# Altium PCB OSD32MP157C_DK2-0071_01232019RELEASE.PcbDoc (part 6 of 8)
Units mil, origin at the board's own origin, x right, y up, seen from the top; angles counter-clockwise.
Board outline 3976.38 x 2795.28 mil, 6 copper layers (Top Layer, Signal Layer 1, Signal Layer 2, Signal Layer 3, Signal Layer 4, Bottom Layer), stack 61.268 mil thick; 404 components, 418 nets, 1720 pads, 1233 vias.
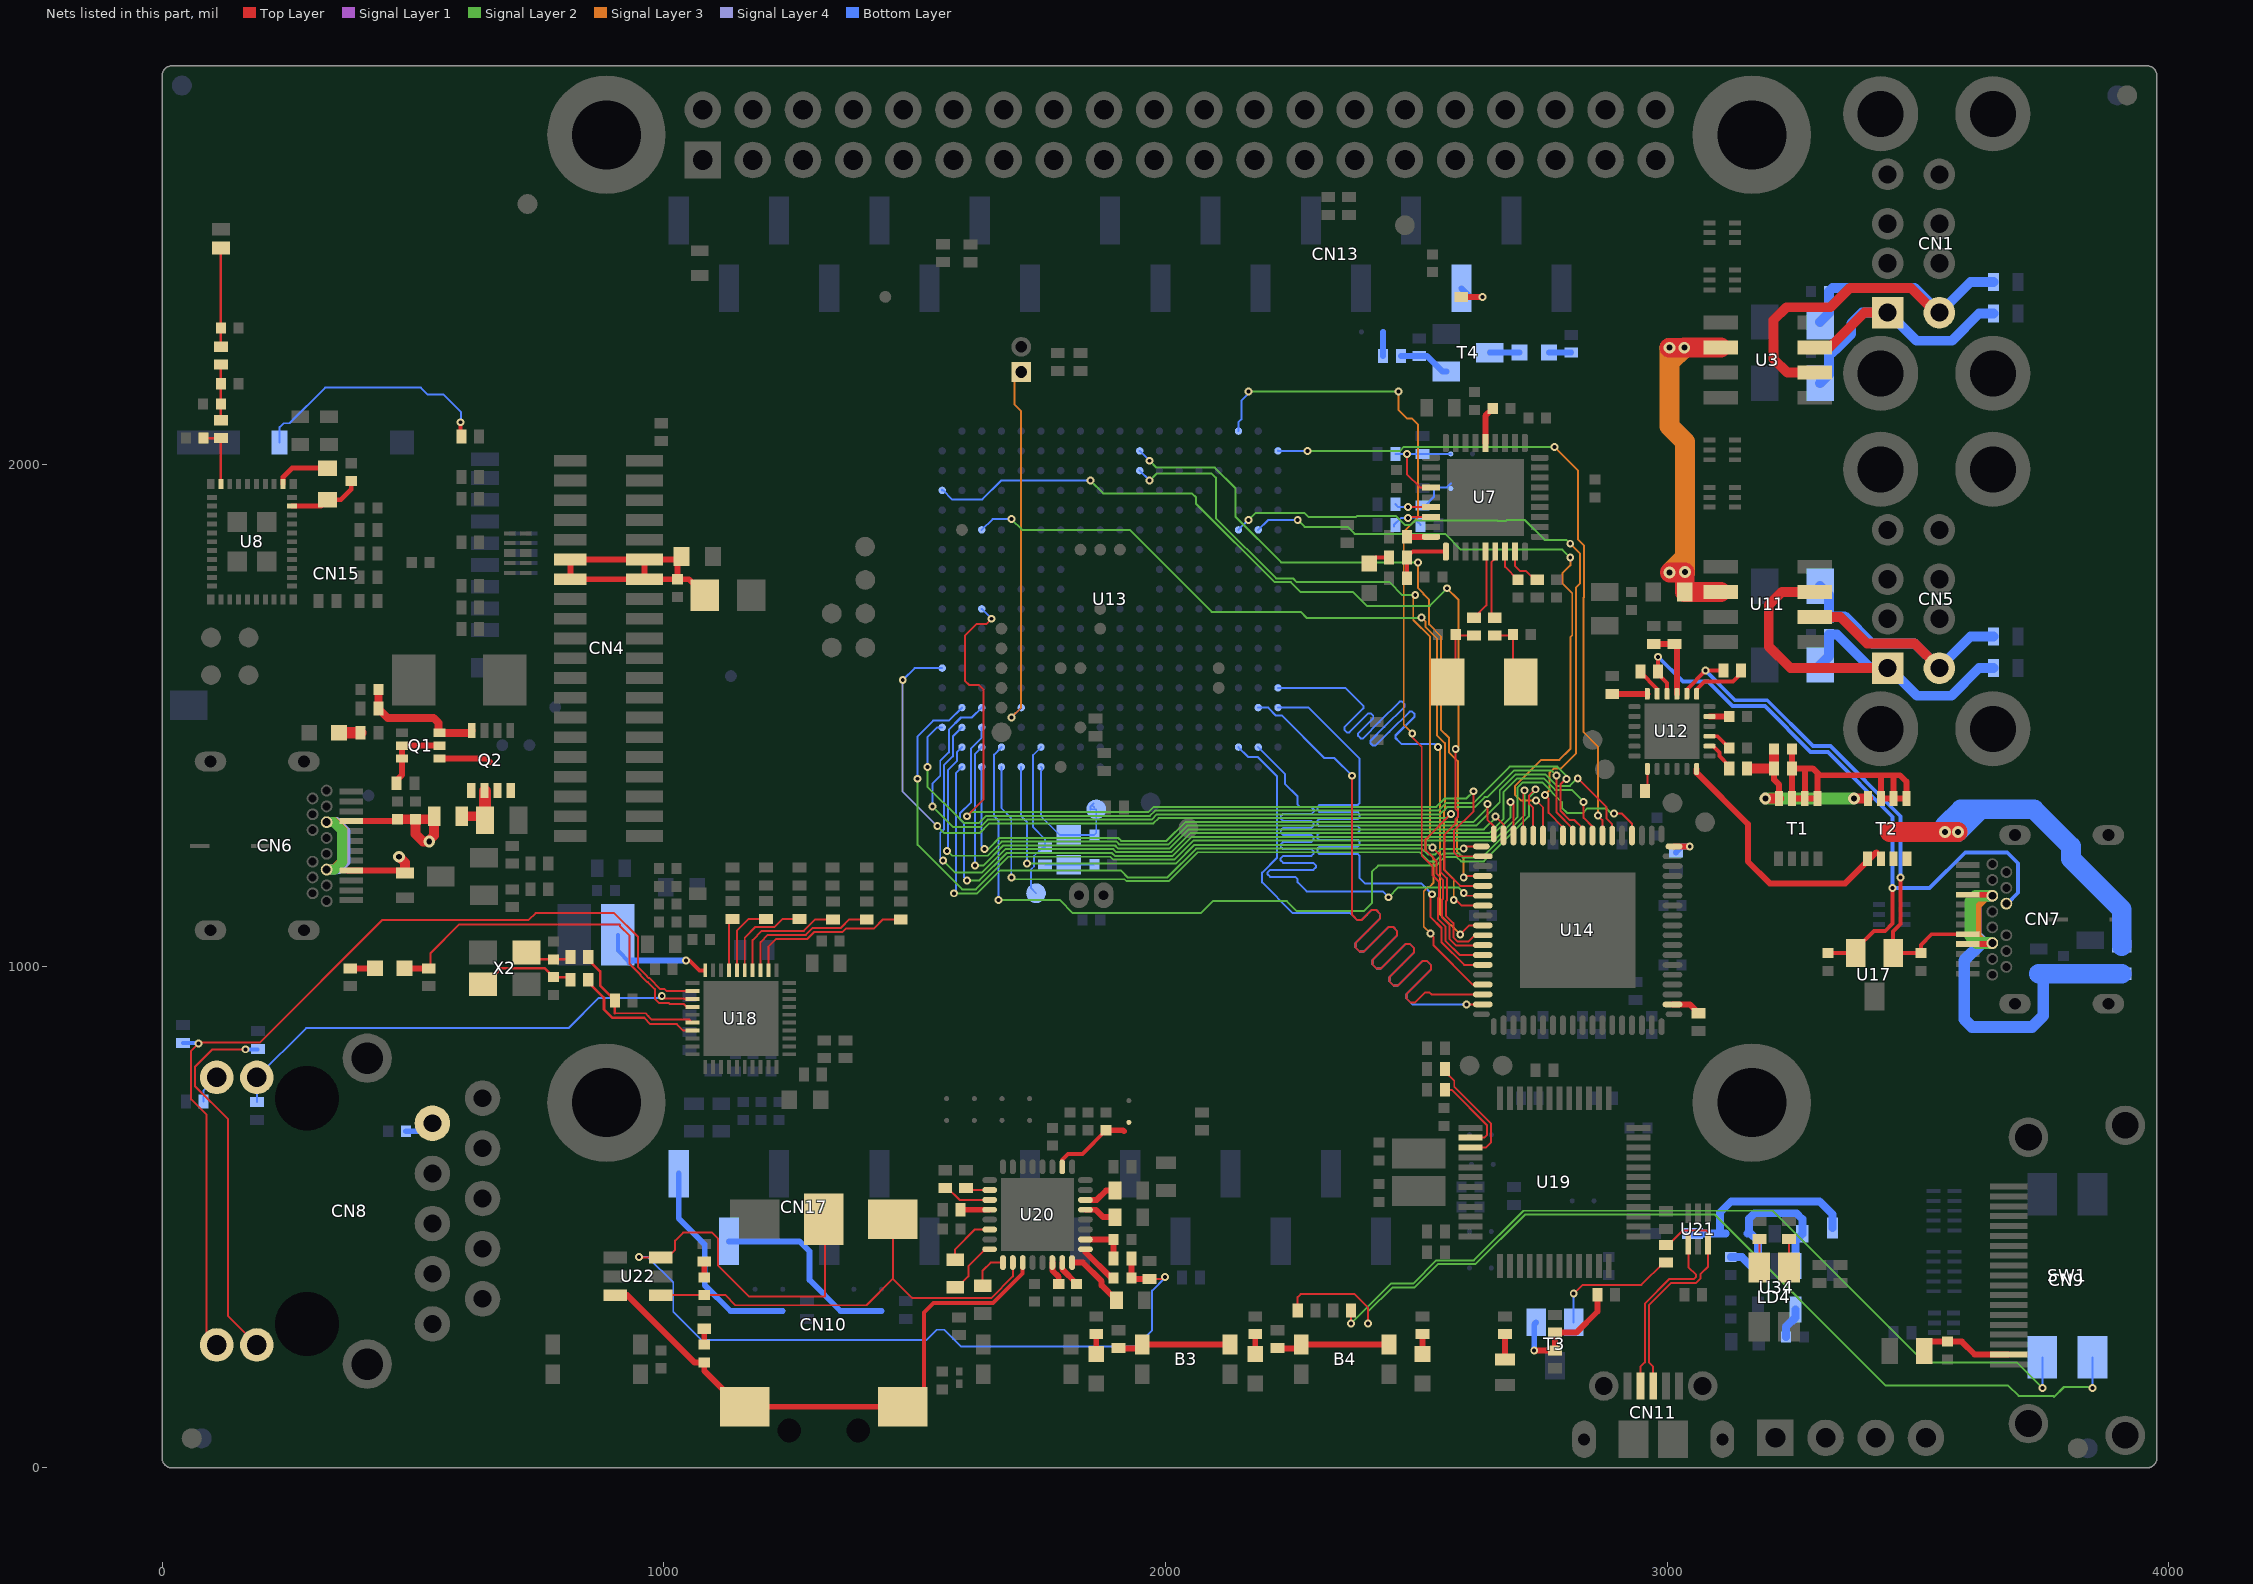
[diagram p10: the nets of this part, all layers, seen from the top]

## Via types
v1: diameter 15.75, hole 7.87, Top Layer to Bottom Layer, tented both sides, 803 vias
v2: diameter 23.62, hole 11.81, Top Layer to Bottom Layer, tented both sides, 417 vias
v3: diameter 15.75, hole 7.87, Top Layer to Bottom Layer, 13 vias

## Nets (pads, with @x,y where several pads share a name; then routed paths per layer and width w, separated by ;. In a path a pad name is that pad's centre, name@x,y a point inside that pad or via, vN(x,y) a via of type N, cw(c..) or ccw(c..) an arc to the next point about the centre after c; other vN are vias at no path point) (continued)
LTDC_B1: U13.A4 U14.31 | length 1444.4
  Top Layer w3.94: v1(2531.49,1143.7) 2531.01,1144.18 2528.62,1144.18 2528.62,1098.2 2550.39,1076.44 2550.39,1048.09 2595.53,1002.95 U14.31@2632.87,1002.95
  Bottom Layer w3.94: U13.A4@2224.41,1515.75 2285.43,1515.75 2386.56,1414.62 2386.56,1342.52 2386.56,1335.55 2386.56,1325.1 2383.07,1321.61 2306.78,1321.61 2303.29,1318.13 2303.29,1311.16 2306.78,1307.68 2383.07,1307.68 2386.56,1304.19 2386.56,1297.22 2383.07,1293.74 2306.63,1293.74 2303.15,1290.26 2303.15,1283.29 2306.63,1279.8 2383.07,1279.8 2386.56,1276.32 2386.56,1269.35 2383.07,1265.87 2306.63,1265.87 2303.15,1262.38 2303.15,1255.41 2306.63,1251.93 2383.07,1251.93 2386.56,1248.44 2386.56,1241.48 2383.07,1237.99 2306.63,1237.99 2303.15,1234.51 2303.15,1227.54 2306.63,1224.06 2383.07,1224.06 2386.56,1220.57 2386.56,1210.63 2386.56,1176.43 2397.64,1165.35 2509.84,1165.35 v1(2531.49,1143.7)
LTDC_B2: U13.C18 U14.30 | length 1636.8
  Top Layer w3.94: v1(2492.13,1464.57) 2492.13,1456.69 2511.02,1437.8 2511.02,1220.87 2532.48,1199.41 2532.48,1181.95 2545.27,1169.16 2545.27,1137.99 2543.26,1135.98 2543.26,1094.7 2558.27,1079.7 2558.27,1051.35 2586.98,1022.64 U14.30@2632.87,1022.64
  Signal Layer 2 w3.94: v1(2165.35,2145.66) v1(2464.56,2145.66)
  Signal Layer 3 w3.94: v1(2464.56,2145.66) 2464.56,2109.37 2481.41,2092.52 2490.91,2092.52 2503.94,2079.49 2503.94,1894.88 2475.14,1866.09 2475.14,1481.55 v1(2492.13,1464.57)
  Bottom Layer w3.94: U13.C18@2145.67,2066.93 2145.67,2084.65 2151.57,2090.55 2151.57,2127.95 2165.35,2141.73 v1(2165.35,2145.66)
LTDC_B3: U13.V6 U14.29 | length 1817.3
  Top Layer w3.94: v1(2569.09,1303.74) 2518.9,1253.54 2518.9,1231.1 2526.97,1223.03 2527.56,1223.03 2540.35,1210.24 2540.35,1185.21 2553.14,1172.42 2553.14,1134.73 2551.14,1132.72 2551.14,1097.97 2566.14,1082.96 2566.14,1054.61 2578.83,1041.93 2632.48,1041.93 U14.29@2632.87,1042.32
  Signal Layer 2 w3.94: v1(1545.28,1279.53) 1559.06,1265.75 1629.38,1265.75 1648.67,1285.04 1975.98,1285.04 1986.42,1295.47 2560.83,1295.47 v1(2569.09,1303.74)
  Signal Layer 4 w3.94: v1(1476.38,1570.87) 1476.38,1348.43 v1(1545.28,1279.53)
  Bottom Layer w3.94: v1(1476.38,1570.87) 1500,1594.49 U13.V6@1555.12,1594.49
LTDC_B4: U13.P1 U14.28 | length 1288.9
  Top Layer w3.94: v1(2532.68,1236.81) 2548.23,1221.26 2548.23,1188.47 2561.02,1175.68 2561.02,1131.47 2559.01,1129.46 2559.01,1101.23 2574.02,1086.22 2574.02,1057.88 2582.09,1049.8 2604.53,1049.8 2616.73,1062.01 U14.28@2632.87,1062.01
  Signal Layer 2 w3.94: v1(1724.41,1204.72) 2020.42,1204.72 2058.02,1242.32 2527.17,1242.32 v1(2532.68,1236.81)
  Bottom Layer w3.94: U13.P1@1712.6,1397.64 1712.6,1299.21 1724.41,1287.4 v1(1724.41,1204.72)
LTDC_B5: U13.A5 U14.27 | length 1331.9
  Top Layer w3.94: v1(2587.8,1063.58) 2605.91,1081.69 U14.27@2632.87,1081.69
  Signal Layer 3 w3.94: v1(2543.31,1437.01) 2547.24,1433.07 2547.24,1104.13 v1(2587.8,1063.58)
  Bottom Layer w3.94: U13.A5@2224.41,1555.12 2358.8,1555.12 2390.03,1523.89 2394.63,1519.29 2394.63,1514.36 2356.69,1476.42 2356.69,1471.49 2361.62,1466.56 2366.54,1466.56 2404.49,1504.51 2409.41,1504.51 2414.34,1499.58 2414.34,1494.65 2384.17,1464.48 2384.17,1459.55 2389.1,1454.62 2394.02,1454.62 2426.66,1487.26 2467.07,1527.67 2472,1527.67 2476.92,1522.74 2476.92,1517.81 2436.52,1477.41 2408.88,1449.77 2408.88,1444.85 2413.81,1439.92 2418.74,1439.92 2446.37,1467.55 2486.78,1507.96 2491.71,1507.96 2496.63,1503.03 2496.63,1498.1 2458.69,1460.16 2458.69,1455.23 2466.08,1447.84 2471.01,1442.91 2537.4,1442.91 v1(2543.31,1437.01)
LTDC_B6: U13.T13 U14.25 | length 1624.4
  Top Layer w3.94: v1(2574.8,1131.89) 2578.33,1131.89 2578.93,1132.49 2590.35,1121.06 U14.25@2632.87,1121.06
  Signal Layer 2 w3.94: v1(1692.91,1891.73) 1714.57,1870.08 1928.94,1870.08 2092.32,1706.69 2269.49,1706.69 2281.3,1694.88 2509.84,1694.88 v1(2510.29,1695.33)
  Signal Layer 3 w3.94: v1(2510.29,1695.33) 2518.11,1687.51 2518.11,1676.97 2541.34,1653.74 2541.34,1460.63 2557.09,1444.88 2557.09,1311.22 2555.31,1309.45 2555.31,1193.25 2574.8,1173.77 v1(2574.8,1131.89)
  Bottom Layer w3.94: U13.T13@1633.86,1870.08 1655.51,1891.73 v1(1692.91,1891.73) ; v1@2572.19,1131.89 v1(2574.8,1131.89)
LTDC_B7: U13.B2 U14.24 | length 1355
  Top Layer w3.94: v1@2594.68,1146.26 2600.2,1140.75 U14.24@2632.87,1140.75
  Signal Layer 2 w3.94: v1(2444.88,1137.8) 2464.56,1157.48 2583.52,1157.48 v1(2594.73,1146.27)
  Bottom Layer w3.94: U13.B2@2185.04,1437.01 2238.18,1383.86 2238.18,1364.18 2263.78,1338.58 2263.78,1327.36 2263.78,1322.48 2268.66,1317.6 2290.94,1317.6 2295.81,1312.72 2295.81,1308.54 2290.94,1303.66 2263.78,1303.66 2234.8,1303.66 2229.92,1298.78 2229.92,1294.6 2234.8,1289.72 2263.78,1289.72 2290.79,1289.72 2295.67,1284.85 2295.67,1280.67 2290.79,1275.79 2263.78,1275.79 2234.8,1275.79 2229.92,1270.91 2229.92,1266.73 2234.8,1261.85 2263.78,1261.85 2290.79,1261.85 2295.67,1256.97 2295.67,1252.79 2290.79,1247.91 2263.78,1247.91 2234.8,1247.91 2229.92,1243.04 2229.92,1238.85 2234.8,1233.98 2263.78,1233.98 2290.79,1233.98 2295.67,1229.1 2295.67,1224.92 2290.79,1220.04 2263.78,1220.04 2234.67,1220.04 2229.79,1215.16 2229.79,1210.98 2234.67,1206.1 2263.78,1206.1 2295.13,1206.1 2300.01,1201.22 2300.01,1197.04 2295.13,1192.17 2263.78,1192.17 2208.65,1192.17 2203.77,1187.29 2203.77,1183.11 2208.65,1178.23 2258.9,1178.23 2263.78,1173.35 2263.78,1171.26 2263.78,1167.32 2281.5,1149.61 2433.07,1149.61 v1(2444.88,1137.8)
LTDC_CLK: U13.H17 U14.22 | length 1387.7
  Top Layer w3.94: v1(2594.68,1176.77) 2598.03,1180.12 U14.22@2632.87,1180.12
  Signal Layer 2 w3.94: v1(1968.5,2007.87) 1982.28,1994.09 2098.43,1994.09 2139.76,1952.76 2139.76,1895.87 2230.51,1805.12 v1(2503.94,1805.12)
  Signal Layer 3 w3.94: v1(2503.94,1805.12) 2503.94,1753.74 2514.76,1742.91 2514.76,1741.68 2525.59,1730.85 2525.59,1681.64 2549.21,1658.02 2549.21,1471.99 2564.96,1456.24 2564.96,1427.17 2582.87,1409.25 2582.87,1298.03 2580.91,1296.06 2580.91,1229.13 2594.68,1215.36 v1(2594.68,1176.77)
  Bottom Layer w3.94: U13.H17@1948.82,2027.56 v1(1968.5,2007.87)
LTDC_DE: U13.H16 U14.33 | length 1583.9
  Top Layer w3.94: v1(2528.74,1065.55) 2527.76,1064.57 2534.65,1057.68 2534.65,1041.57 2612.63,963.58 U14.33@2632.87,963.58
  Signal Layer 2 w3.94: v1(1968.5,1968.5) 1982.28,1982.28 2092.32,1982.28 2100.39,1974.21 2100.39,1893.7 2220.87,1773.23 2254.33,1773.23 2261.81,1765.75 2446.85,1765.75 2472.44,1740.16 v1(2498.03,1740.16)
  Signal Layer 3 w3.94: v1(2498.03,1740.16) 2494.09,1736.22 2494.09,1690.41 2527.56,1656.95 2527.56,1259.25 2518.9,1250.59 2518.9,1231.1 2534.68,1215.32 2534.68,1167.14 2525.63,1158.08 2523.07,1158.08 2515,1150.01 2515,1079.29 v1(2528.74,1065.55)
  Bottom Layer w3.94: U13.H16@1948.82,1988.19 v1(1968.5,1968.5)
LTDC_G0: U13.V15 U14.23 | length 1833.5
  Top Layer w3.94: v1(2578.74,1433.07) 2578.74,1313.58 2582.87,1309.45 2582.87,1298.03 2578.74,1293.9 2578.74,1285.15 2556.1,1262.51 2556.1,1191.73 2587.4,1160.43 U14.23@2632.87,1160.43
  Signal Layer 2 w3.94: v1(1850.39,1968.5) 1875.98,1942.91 2052.95,1942.91 2061.02,1934.84 2061.02,1922.49 2217.77,1765.75 2250,1765.75 2269.68,1746.06 2374.02,1746.06 2401.57,1718.5 2527.02,1718.5 2561.25,1752.73 v1(2561.25,1753.71)
  Signal Layer 3 w3.94: v1(2561.25,1753.71) 2584.65,1730.31 2584.65,1438.98 v1(2578.74,1433.07)
  Bottom Layer w3.94: U13.V15@1555.12,1950.79 U13.V15@1555.12,1948.82 1556.81,1948.82 1574.53,1931.1 1634.93,1931.1 1672.33,1968.5 v1(1850.39,1968.5)
LTDC_G1: U13.T9 U14.20 | length 1729.5
  Top Layer w3.94: v1(1604.33,1299.21) 1637.8,1332.68 1637.8,1551.18 1627.95,1561.02 1608.47,1561.02 1600.39,1569.1 1600.39,1659.34 1623.34,1682.28 1642.91,1682.28 v1(1653.54,1692.91) ; v1(2614.37,1349.02) 2614.37,1309.65 2575.1,1270.37 2575.1,1227.07 2582.68,1219.49 U14.20@2632.87,1219.49
  Signal Layer 2 w3.94: v1(1604.33,1299.21) 1612.6,1307.48 1966.13,1307.48 1976.57,1317.91 2540.35,1317.91 2557.01,1334.57 2599.93,1334.57 v1(2614.37,1349.02)
  Bottom Layer w3.94: U13.T9@1633.86,1712.6 v1(1653.54,1692.91) v1@1653.54,1688.98
LTDC_G2: U13.U1 U14.19 | length 1369.6
  Top Layer w3.94: v1(2594.68,1234.84) 2599.02,1239.17 U14.19@2629.92,1239.17
  Signal Layer 2 w3.94: v1(1578.74,1145.67) 1624.68,1145.67 1669.95,1190.94 1911.61,1190.94 1925.39,1177.16 2003.44,1177.16 2061.12,1234.84 2511.22,1234.84 2523.03,1223.03 2538.38,1223.03 2549.21,1233.86 2593.7,1233.86 v1(2594.68,1234.84)
  Bottom Layer w3.94: v1(1578.74,1145.67) 1582.68,1149.61 1582.68,1385.83 U13.U1@1594.49,1397.64
LTDC_G3: U13.T1 U14.18 | length 1279.3
  Top Layer w3.94: v1(2641.93,1323.43) 2641.93,1292.4 2654.53,1279.8 U14.18@2654.53,1263.78
  Signal Layer 2 w3.94: v1(1639.76,1234.25) 1647.44,1234.25 1669.09,1255.91 1905.71,1255.91 1911.62,1250 2002.22,1250 2040.22,1287.99 2614.37,1287.99 2641.93,1315.55 v1(2641.93,1323.43)
  Bottom Layer w3.94: U13.T1@1633.86,1397.64 1633.86,1240.16 v1(1639.76,1234.25)
LTDC_G4: U13.T2 U14.17 | length 1372.1
  Top Layer w3.94: v1(2657.72,1298.83) 2657.72,1298.77 2674.21,1282.28 U14.17@2674.21,1260.83
  Signal Layer 2 w3.94: v1(1620.57,1200.79) 1636.92,1200.79 1677.08,1240.94 1899.51,1240.94 1905.42,1235.04 2008.42,1235.04 2046.41,1273.03 2634.84,1273.03 2659.18,1297.37 v1(2657.72,1298.83)
  Bottom Layer w3.94: v1(1620.57,1200.79) 1620.57,1423.72 U13.T2@1633.86,1437.01
LTDC_G5: U13.T3 U14.16 | length 1589.6
  Top Layer w3.94: U14.16@2693.9,1260.83 2693.9,1321.95 v1(2688.19,1327.66) ; v1(2688.19,1327.66) 2683.96,1331.89 2683.96,1323.43 v1(2688.19,1327.66)
  Signal Layer 2 w3.94: v1(1604.33,1171.26) 1629.11,1171.26 1683.83,1225.98 1893.32,1225.98 1899.22,1220.08 2014.62,1220.08 2052.61,1258.07 2648.85,1258.07 2688.19,1297.41 v1(2688.19,1327.66)
  Bottom Layer w3.94: v1(1604.33,1171.26) 1598.43,1177.17 1598.43,1285.63 1590.55,1293.51 1590.55,1304.92 1612.7,1327.07 1612.7,1434.64 1633.86,1455.8 U13.T3@1633.86,1476.38
LTDC_G6: U13.R1 U14.15 | length 1472.3
  Top Layer w3.54: U14.15@2713.58,1260.83 2713.58,1348.82 v1(2715.75,1350.98)
  Signal Layer 2 w3.54: v1(1692.91,1177.16) 1696.25,1173.82 1918.43,1173.82 1922.37,1169.88 2006.46,1169.88 2064.13,1227.56 2506.69,1227.56 2525.59,1208.66
  Signal Layer 2 w3.94: 2525.59,1208.66 2536.7,1208.66 2553.43,1225.39 2584.42,1225.39 2592.69,1217.13 2631.78,1217.13 2715.75,1301.1 v1(2715.75,1350.98)
  Bottom Layer w3.54: U13.R1@1673.23,1397.64 1673.23,1314.96 1692.91,1295.28 v1(1692.91,1177.16)
LTDC_G7: U13.R2 U14.14 | length 1684.3
  Top Layer w3.94: U14.14@2733.27,1260.83 2733.27,1315.95 2724.61,1324.61 2724.61,1340.16 v1(2737.42,1352.97)
  Signal Layer 2 w3.94: v1(1667.32,1131.89) 1789.93,1131.89 1815.53,1106.3 2070.87,1106.3 2094.49,1129.92 2242.32,1129.92 2262.01,1110.24 2395.67,1110.24 2411.42,1125.98 2411.42,1188.3 2423.9,1200.79 2539.4,1200.79 2556.14,1217.52 2581.16,1217.52 2589.42,1209.25 2635.04,1209.25 2724.61,1298.82 2724.61,1336.02 2739.42,1350.83 2737.42,1352.83 v1(2737.42,1352.97)
  Bottom Layer w3.94: v1(1667.32,1131.89) 1667.32,1289.96 1658.46,1298.82 1658.46,1422.24 U13.R2@1673.23,1437.01
LTDC_HSYNC: U13.B4 U14.34 | length 1439.9
  Top Layer w3.94: v1(2372.04,1379.92) 2372.04,1102.37 2374.02,1100.39 2382.41,1092 2390.87,1092 2411.36,1112.49 2419.82,1112.49 2428.29,1104.03 2428.29,1095.56 2403.57,1070.84 2378.85,1046.12 2378.85,1037.66 2387.31,1029.2 2395.77,1029.2 2420.49,1053.92 2445.21,1078.64 2453.68,1078.64 2462.14,1070.17 2462.14,1061.71 2437.42,1036.99 2412.7,1012.27 2412.7,1003.81 2421.16,995.34 2429.62,995.34 2454.34,1020.06 2479.07,1044.79 2487.53,1044.79 2495.99,1036.32 2495.99,1027.86 2471.27,1003.14 2446.55,978.42 2446.55,969.95 2455.01,961.49 2463.48,961.49 2488.2,986.21 2512.92,1010.93 2521.38,1010.93 2529.84,1002.47 2529.84,994.01 2505.12,969.29 2480.4,944.57 2480.4,936.1 2488.86,927.64 2497.33,927.64 2517.82,948.13 2526.28,948.13 2530.51,943.9 U14.34@2632.87,943.9
  Bottom Layer w3.94: U13.B4@2185.04,1515.75 2205.62,1515.75 2205.62,1514.66 2220.47,1499.8 2232.48,1499.8 2316.93,1415.35 2326.77,1415.35 2336.61,1415.35 v1(2372.04,1379.92)
LTDC_R0: U13.B13 U14.13 | length 1340.7
  Top Layer w3.54: v1(2738.39,1330.31) 2738.39,1331.3 2752.95,1316.73 U14.13@2752.95,1260.83
  Signal Layer 2 w3.94: v1(2263.78,1889.76) 2277.56,1875.98 2363.5,1875.98 2377.28,1862.2 2557.62,1862.2 2589.12,1830.71 2791.34,1830.71 v1(2807.09,1814.96)
  Signal Layer 3 w3.94: v1(2738.39,1330.31) 2709.06,1330.31 2696.85,1342.52 2696.85,1358.88 2749.39,1411.42 2785.24,1411.42 2807.09,1433.27 2807.09,1655.71 2811.02,1659.65 2811.02,1743.65 2791.34,1763.33 2791.34,1783.46 2807.09,1799.21 v1(2807.09,1814.96)
  Bottom Layer w3.94: U13.B13@2185.04,1870.08 2204.72,1889.76 v1(2263.78,1889.76)
LTDC_R1: U13.C13 U14.11 | length 1355.3
  Top Layer w3.94: v1(2756.32,1341.91) 2763.78,1334.45 2763.78,1305.91 2792.32,1277.36 U14.11@2792.32,1260.83
  Signal Layer 2 w3.94: v1(2165.35,1889.76) 2179.13,1903.54 2277.76,1903.54 2285.63,1895.67 2379.47,1895.67 2381.44,1897.64 2459.84,1897.64 2477.56,1879.92 2488.98,1879.92 2497.83,1888.78 2661.95,1888.78 2662.94,1887.8 2678.6,1887.8 2680.57,1889.76 2716.54,1889.76 2755.91,1850.39 2799.21,1850.39 v1(2807.09,1842.52)
  Signal Layer 3 w3.94: v1(2756.32,1341.91) 2765.94,1351.53 2765.94,1386.22 2774.02,1394.29 2787.99,1394.29 2818.9,1425.2 2818.9,1755.46 2826.77,1763.33 2826.77,1822.83 v1(2807.09,1842.52)
  Bottom Layer w3.94: U13.C13@2145.67,1870.08 v1(2165.35,1889.76) ; v1@2754.92,1340.51 v1(2756.32,1341.91)
LTDC_R2: U13.T4 U14.10 | length 1695.6
  Top Layer w3.94: v1(2779.72,1380.51) 2779.72,1306.69 2812.01,1274.41 U14.10@2812.01,1260.83
  Signal Layer 2 w3.94: v1(1535.43,1318.9) 1576.77,1277.56 1630.62,1277.56 1645.57,1292.52 1972.33,1292.52 1982.76,1302.95 2547.05,1302.95 2561.61,1317.52 2616.54,1317.52 2636.22,1337.2 2641.71,1337.2 2694.87,1390.37 2769.86,1390.37 v1(2779.72,1380.51)
  Bottom Layer w3.94: v1(1535.43,1318.9) 1535.43,1364.17 1551.18,1379.92 1551.18,1409.45 1568.41,1426.67 1568.41,1471.95 1592.52,1496.06 1614.17,1496.06 U13.T4@1633.86,1515.75
LTDC_R3: U13.V3 U14.9 | length 1642.8
  Top Layer w3.94: v1(2799.41,1373.62) 2798.43,1373.62 2787.6,1362.8 2787.6,1309.95 2805.47,1292.08 2814.55,1292.08 2831.69,1274.95 U14.9@2831.69,1260.83
  Signal Layer 2 w3.94: v1(1525.59,1397.64) 1525.59,1358.27 1588.58,1295.28 1588.78,1295.28 1598.62,1285.43 1627.91,1285.43 1642.47,1300 1969.23,1300 1979.66,1310.43 2543.95,1310.43 2558.91,1325.39 2613.27,1325.39 2686.13,1398.25 2781.48,1398.25 2799.41,1380.31 v1(2799.41,1373.62)
  Bottom Layer w3.94: v1(1525.59,1397.64) 1525.59,1456.69 1545.28,1476.38 U13.V3@1555.12,1476.38
LTDC_R4: U13.U3 U14.8 | length 1799.3
  Top Layer w3.94: v1(2833.86,1327.36) 2833.86,1295.87 2851.38,1278.35 U14.8@2851.38,1260.83
  Signal Layer 2 w3.94: v1(1557.09,1210.63) 1580.71,1187.01 1634.28,1187.01 1680.73,1233.46 1896.41,1233.46 1902.32,1227.56 2011.52,1227.56 2049.51,1265.55 2645.75,1265.55 2674.41,1294.21 2674.41,1347.64 2701.4,1374.62 2754.23,1374.62 2776.88,1351.97 2810.24,1351.97 2834.84,1327.36 v1(2833.86,1327.36)
  Bottom Layer w3.94: v1(1557.09,1210.63) 1561.02,1210.63 1555.12,1204.73 1551.18,1208.67 1551.18,1265.95 1559.06,1273.82 1559.06,1401.57 1576.28,1418.8 1576.28,1458.17 U13.U3@1594.49,1476.38
LTDC_R5: U13.A17 U14.7 | length 1371
  Top Layer w3.94: v1(2862.3,1300.43) 2871.06,1291.67 U14.7@2871.06,1260.83
  Signal Layer 2 w3.94: v1(2283.46,2027.56) 2467.72,2027.56 2475.59,2035.43 v1(2775.59,2035.43)
  Signal Layer 3 w3.94: v1(2775.59,2035.43) 2822.83,1988.19 2822.83,1850.59 2834.65,1838.78 2834.65,1736.22 2833.07,1734.65 2833.07,1467.37 2862.2,1438.24 2862.2,1300.53 v1(2862.3,1300.43)
  Bottom Layer w3.94: U13.A17@2224.41,2027.56 2224.41,2028.35 2225.2,2027.56 v1(2283.46,2027.56)
LTDC_R6: U13.U2 U14.6 | length 1725
  Top Layer w3.94: v1(2822.05,1374.61) 2879.54,1317.11 2879.54,1294.28 2890.75,1283.07 U14.6@2890.75,1260.83
  Signal Layer 2 w3.94: v1(1564.96,1230.31) 1574.8,1220.47 1645.47,1220.47 1673.42,1248.43 1902.61,1248.43 1908.52,1242.52 2005.32,1242.52 2043.32,1280.51 2619.69,1280.51 2666.54,1327.36 2666.54,1350.9 2698.13,1382.5 2757.49,1382.5 2780.14,1359.84 2806.3,1359.84 2822.05,1375.59 v1(2822.05,1374.61)
  Bottom Layer w3.94: v1(1564.96,1230.31) 1566.93,1232.28 1566.93,1391.73 1584.15,1408.96 1584.15,1426.67 U13.U2@1594.49,1437.01
LTDC_R7: U13.U4 U14.4 | length 1988.6
  Top Layer w3.94: v1(2893.95,1304.74) 2909.63,1304.74 2930.12,1284.25 U14.4@2930.12,1260.83
  Signal Layer 2 w3.94: v1(1505.91,1374.02) 1505.91,1242.32 1594.69,1153.54 1621.97,1153.54 1686.93,1218.5 1890.22,1218.5 1896.13,1212.6 2017.71,1212.6 2055.71,1250.59 2654.11,1250.59 2701.97,1298.45 2701.97,1356.69 2712.03,1366.75 2750.97,1366.75 2790.55,1327.16 2790.55,1316.09 2800.93,1305.71 2831.69,1305.71 2840.94,1314.96 2878.4,1314.96 2888.62,1304.74 v1(2893.95,1304.74)
  Bottom Layer w3.94: v1(1505.91,1374.02) 1505.91,1458.66 1536.91,1489.67 1568.41,1489.67 U13.U4@1594.49,1515.75
LTDC_VSYNC: U13.C2 U14.35 | length 1440.4
  Top Layer w3.94: v1(2600.39,924.21) U14.35@2632.87,924.21
  Bottom Layer w3.94: U13.C2@2145.67,1437.01 2165.35,1417.32 2184.15,1417.32 2222.44,1379.03 2222.44,1216.54 2192.91,1187.01 2192.91,1167.32 2253.94,1106.3 2368.11,1106.3 2382.41,1092 2390.87,1092 2411.36,1112.49 2419.82,1112.49 2428.29,1104.03 2428.29,1095.56 2378.85,1046.12 2378.85,1037.66 2387.31,1029.2 2395.77,1029.2 2445.21,1078.64 2453.68,1078.64 2462.14,1070.17 2462.14,1061.71 2412.7,1012.27 2412.7,1003.81 2421.16,995.34 2429.62,995.34 2479.07,1044.79 2487.53,1044.79 2495.99,1036.32 2495.99,1027.86 2446.55,978.42 2446.55,969.95 2455.01,961.49 2463.48,961.49 2512.92,1010.93 2521.38,1010.93 2529.84,1002.47 2529.84,994.01 2480.4,944.57 2480.4,936.1 2492.29,924.21 v1(2600.39,924.21)
NetB3_3: B3.3 B3.4 R110.1 | length 226.1
  Top Layer w11.81: R110.1@1906.5,239.17 1907.48,238.19 1945.87,238.19 B3.4@1953.74,246.06 B3.3@2128.94,246.06
NetB4_3: B4.3 B4.4 R111.1 | length 226.1
  Top Layer w11.81: R111.1@2223.43,239.17 2224.41,238.19 2262.8,238.19 B4.4@2270.67,246.06 B4.3@2445.87,246.06
NetC8_2: C8.2 L1.1 R8.1 | length 196.9
  Top Layer w5.12: R8.1@117.13,2235.24 C8.2@117.13,2272.64 L1.1@117.13,2432.09
NetC19_2: C19.2 C24.2 R8.2 R10.1 | length 111.2
  Top Layer w5.12: R10.1@117.13,2088.58 C24.2@117.13,2121.06 C19.2@117.13,2161.42 R8.2@117.13,2199.8
NetC25_2: C25.2 U7.14 | length 75
  Top Layer w11.81: U7.14@2637.8,2043.31 2637.8,2097.44 C25.2@2652.56,2112.2
NetC34_2: C34.2 R10.2 U8.41 | length 133.9
  Top Layer w5.12: C34.2@74.8,2053.15 R10.2@117.13,2053.15 117.13,2020.67 U8.41@117.13,1961.61
NetC37_2: C37.2 L4.2 U8.31 | length 148.7
  Top Layer w9.84: U8.31@258.86,1917.32 316.93,1917.32 L4.2@329.72,1930.12 356.3,1930.12 376.97,1950.79 C37.2@376.97,1967.52
NetC51_2: C51.2 C52.1 CN4.27 CN4.28 CN4.29 CN4.30 L7.2 | length 623.6
  Top Layer w11.81: L7.2@1035.43,1816.93 L7.2@1029.53,1811.02 ; C52.1@1081.69,1740.16 1050.2,1771.65 C51.2@1027.56,1771.65 ; CN4.27@961.61,1771.65 CN4.29@961.61,1811.02 ; CN4.27@961.61,1771.65 C51.2@1027.56,1771.65 ; CN4.27@961.61,1771.65 CN4.28@813.98,1771.65 CN4.30@813.98,1811.02 CN4.29@961.61,1811.02 ; CN4.29@961.61,1811.02 L7.2@1029.53,1811.02 ; C51.2@1027.56,1771.65 1027.56,1809.06 L7.2@1029.53,1811.02
NetC53_2: C53.2 U7.34 | length 66.7
  Top Layer w3.94: U7.34@2677.17,1826.77 2677.17,1796.26 C53.2@2702.76,1770.67
NetC58_2: C58.2 R29.1 X1.1 | length 138.2
  Top Layer w3.94: X1.1@2562.99,1566.93 2578.74,1582.68 C58.2@2578.74,1661.42 2580.71,1659.45 R29.1@2615.16,1659.45
NetC59_2: C59.2 R30.1 X1.2 | length 138.2
  Top Layer w3.94: R30.1@2656.5,1659.45 2690.94,1659.45 C59.2@2692.91,1661.42 2692.91,1582.68 X1.2@2708.66,1566.93
NetC61_1: C61.1 Q1.3 Q2.4 R39.2 | length 256.8
  Top Layer w15.75: C61.1@431.1,1552.17 R39.2@431.1,1513.78 449.8,1495.08 541.34,1495.08 551.18,1485.24 551.18,1467.52 Q1.3@553.15,1465.55 612.2,1465.55 Q2.4@617.13,1470.47
NetC62_2: C62.2 U12.23 | length 39.4
  Top Layer w11.81: U12.23@3084.65,1498.03 C62.2@3124.02,1498.03
NetC65_2: C65.2 U12.21 | length 49.2
  Top Layer w7.87: U12.21@3084.65,1458.66 3100.39,1458.66 C65.2@3124.02,1435.04
NetC66_1: C66.1 R42.1 R43.1 T1.4 T2.4 | length 388.9
  Top Layer w11.81: R42.1@3213.58,1394.69 3213.58,1372.05 3223.43,1362.2 T1.4@3223.43,1334.65
  Top Layer w19.68: R43.1@3159.45,1394.68 R42.1@3213.58,1394.69 C66.1@3213.58,1433.07 ; v2(3195.87,1334.65) T1.4@3223.43,1334.65 ; v2(3373.03,1334.65) T2.4@3400.59,1334.65
  Signal Layer 2 w23.62: v2(3195.87,1334.65) v2(3373.03,1334.65)
NetC66_2: C66.2 R42.2 T1.1 T1.2 T1.3 T2.1 T2.2 T2.3 | length 678.4
  Top Layer w11.81: C66.2@3249.02,1433.07 R42.2@3249.02,1394.69 ; R42.2@3249.02,1394.69 3275.59,1394.69 ; R42.2@3249.02,1394.69 T1.3@3249.02,1334.65 T1.2@3274.61,1334.65 ; T1.2@3274.61,1334.65 T1.1@3300.2,1334.65 3300.2,1384.84 ; T1.2@3274.61,1334.65 3274.61,1393.7 3275.59,1394.69 ; 3275.59,1394.69 3290.35,1394.69 3300.2,1384.84 ; 3300.2,1384.84 3304.13,1380.91 3428.15,1380.91 ; 3428.15,1380.91 3449.8,1380.91 ; 3428.15,1380.91 3426.18,1378.94 T2.3@3426.18,1334.65 T2.2@3451.77,1334.65 ; 3449.8,1380.91 3464.57,1380.91 3477.36,1368.11 T2.1@3477.36,1334.65 T2.2@3451.77,1334.65 ; 3449.8,1380.91 3451.77,1378.94 T2.2@3451.77,1334.65
NetC69_2: C69.2 C70.1 CN6.A4 CN6.A9 CN6.B4 CN6.B9 R47.1 U16.1 | length 1019.2
  Top Layer w11.81: CN6.A9@369.29,1190.94 CN6.A9@377.17,1190.94 479.33,1190.94 U16.1@484.25,1186.02 ; CN6.A4@369.29,1289.37 CN6.A4@377.17,1289.37 465.55,1289.37 C69.2@469.49,1293.31 ; R47.1@536.42,1293.31 R47.1@542.32,1299.21
  Top Layer w19.68: C69.2@469.49,1293.31 C70.1@504.92,1293.31 ; v2(472.44,1218.5) 484.25,1206.69 U16.1@484.25,1186.02 ; R47.1@536.42,1293.31 C70.1@504.92,1293.31 ; R47.1@542.32,1299.21 542.32,1260.83 532.48,1250.98 v2(532.48,1249.02) 519.69,1249.02 504.92,1263.78 C70.1@504.92,1293.31
  Signal Layer 2 w19.68: CN6.B9@327.17,1287.4 CN6.B9@327.95,1287.4 341.73,1287.4 358.46,1270.67 358.46,1206.69 344.68,1192.91 CN6.B4@327.95,1192.91
  Signal Layer 3 w19.68: CN6.B4@327.95,1192.91 342.52,1192.91 359.25,1209.65 359.25,1271.65 343.5,1287.4 CN6.B9@327.95,1287.4
  Signal Layer 4 w19.68: CN6.B4@326.97,1192.91 327.95,1193.9 351.57,1193.9 365.35,1207.68 365.35,1269.69 347.64,1287.4 CN6.B9@327.95,1287.4 CN6.B9@327.17,1287.4
  Bottom Layer w19.68: CN6.B4@327.95,1192.91 346.46,1192.91 360.24,1206.69 360.24,1271.65 344.49,1287.4 CN6.B9@327.95,1287.4
NetC71_2: C71.2 Q1.1 Q2.5 Q2.6 Q2.7 Q2.8 R47.2 | length 212.2
  Top Layer w11.81: Q1.1@553.15,1414.37 646.65,1414.37 653.54,1407.48
  Top Layer w19.68: R47.2@597.44,1299.21 635.83,1299.21 C71.2@643.7,1291.34 ; Q2.6@642.72,1350.39 Q2.6@643.7,1349.41
  Top Layer w23.62: C71.2@643.7,1291.34 Q2.6@643.7,1349.41
NetC82_2: C82.2 R64.1 X2.1 | length 95.3
  Top Layer w5.12: X2.1@726.38,1027.56 740.16,1013.78 C82.2@780.51,1013.78 809.06,1013.78 R64.1@813.98,1018.7
NetC83_2: C83.2 CN7.B5 R35.2 U12.4 U17.2 | length 1431.4
  Top Layer w7.87: v1(2982.28,1617.13) R35.2@2982.28,1587.6 2982.28,1582.68 3000,1564.96 U12.4@3000,1543.31 ; C83.2@3320.87,1026.57 U17.2@3375.98,1026.57 3375.98,1034.45 3412.4,1070.87 3435.04,1070.87 3449.8,1085.63 v1(3449.8,1156.5)
  Bottom Layer w7.87: v1(2982.28,1617.13) 3031.5,1567.91 3081.72,1567.91 3130.93,1518.7 3194.88,1518.7 3286.42,1427.17 3320.9,1427.17 3449.8,1298.26 v1(3449.8,1156.5) 3523.62,1156.5 3594.49,1227.36 3678.15,1227.36 3700,1205.51 3700,1146.71 3678.29,1125 CN7.B5@3676.38,1125
NetC84_2: C84.2 CN7.A5 R34.2 U12.2 U17.1 | length 1058.1
  Top Layer w7.87: U12.2@3039.37,1543.31 3039.37,1552.17 v1(3076.77,1589.57) R34.2@3112.2,1589.57 ; v1(3465.55,1177.17) 3465.55,1084.67 3450.79,1069.91 U17.1@3450.79,1026.57 C84.2@3505.91,1026.57 3505.91,1042.32 3527.56,1063.98 CN7.A5@3599.21,1063.98
  Bottom Layer w7.87: v1(3076.77,1589.57) 3135.83,1530.51 3199.77,1530.51 3291.31,1438.98 3325.79,1438.98 3465.55,1299.21 v1(3465.55,1177.17)
NetC86_2: C86.2 R68.1 X2.3 | length 196.6
  Top Layer w5.12: X2.3@639.76,964.57 643.7,964.57 675.2,996.06 762.8,996.06 C86.2@780.51,978.35 809.06,978.35 R68.1@813.98,973.43
NetC90_1: C90.1 TP30.1 U13.N1 X4.1 | length 306.8
  Bottom Layer w3.54: U13.N1@1751.97,1397.64 1754.12,1395.49 1754.12,1391.84 1751.96,1389.68 1751.96,1299.22 1789.37,1261.81 X4.1@1807.09,1261.81 C90.1@1858.27,1261.81 1862.2,1265.75 TP30.1@1862.2,1312.99 TP30.1@1850.39,1312.99 ; TP30.1@1853.64,1321.56 TP30.1@1858.27,1316.93
  Bottom Layer w3.94: TP30.1@1850.39,1312.99 1850.39,1318.32 1853.64,1321.56 TP30.1@1856.3,1324.22
NetC91_1: C91.1 R71.2 X4.2 | length 98.4
  Bottom Layer w3.54: R71.2@1759.84,1202.76 X4.2@1807.09,1202.76 C91.1@1858.27,1202.76
NetC96_1: C96.1 SB5.2 U20.26 | length 162.1
  Top Layer w7.87: U20.26@1794.29,600.39 1794.29,614.17 1806.1,625.98 1834.65,625.98 C96.1@1881.89,673.23
  Top Layer w11.81: C96.1@1881.89,673.23 1915.35,673.23 1917.32,671.26
NetC100_2: C100.2 U20.22 | length 66.8
  Top Layer w11.81: U20.22@1840.55,534.45 1863.19,534.45 1881.89,553.15 C100.2@1899.61,553.15
NetC101_2: C101.2 U20.21 | length 65.2
  Top Layer w11.81: U20.21@1840.55,514.76 1861.22,514.76 1875.98,500 C101.2@1899.61,500
NetC103_2: C103.2 R95.2 U20.18 | length 94.5
  Top Layer w11.81: U20.18@1840.55,455.71 C103.2@1896.65,455.71 R95.2@1896.65,417.32
NetC104_1: C104.1 U20.8 | length 112.4
  Top Layer w3.94: C104.1@1580.71,360.24 1585.63,360.24 1607.28,381.89 1607.28,402.56 1640.75,436.02 U20.8@1649.61,436.02
NetC104_2: C104.2 U20.6 | length 105.9
  Top Layer w3.94: C104.2@1580.71,415.35 1580.71,436.02 1620.08,475.39 U20.6@1649.61,475.39
NetC105_1: C105.1 CN10.1 R95.1 R96.2 U22.3 | length 2028.6
  Top Layer w3.94: v1(950.79,420.28) 951.77,419.29 U22.3@994.09,419.29 1006.89,419.29 1022.64,435.04 1022.64,453.15 1038.58,469.09 1096.65,469.09 1108.46,457.28 1108.46,403.35 1170.28,341.54 1321.46,341.54 1321.46,493.5 CN10.1@1318.9,496.06 ; R96.2@1968.5,376.97 1968.9,376.57 1995.24,376.57 v1(1999.21,380.55)
  Top Layer w11.81: R95.1@1932.09,417.32 C105.1@1932.09,378.94 1934.06,376.97 R96.2@1968.5,376.97
  Bottom Layer w3.94: v1(950.79,420.28) 968.5,420.28 1018.9,369.88 1018.9,311.61 1075.59,254.92 1523.37,254.92 1544.04,275.59 1558.86,275.59 1592.72,241.73 1940.55,241.73 1973.43,274.61 1973.43,353.35 1999.21,379.13 v1(1999.21,380.55)
NetC105_2: C105.2 U20.17 | length 83.2
  Top Layer w11.81: U20.17@1840.55,436.02 1840.55,430.12 1891.73,378.94 C105.2@1896.65,378.94
NetC106_1: C106.1 R92.2 | length 31.5
  Top Layer w11.81: C106.1@1080.71,379.92 R92.2@1080.71,411.42
NetC106_2: C106.2 CN10.3 U20.10 U22.1 | length 912.8
  Top Layer w3.94: U22.1@994.09,344.49 C106.2@1080.71,344.49 1081.3,345.08 1122.24,345.08 1142.91,324.41 1404.13,324.41 1456.69,376.97 ; CN10.3@1456.69,496.06 1456.69,376.97 ; U20.10@1695.87,409.45 1695.87,382.03 1652.42,338.58 1495.08,338.58 1456.69,376.97
NetC108_2: C108.2 U20.14 | length 47.6
  Top Layer w11.81: U20.14@1774.61,409.45 1774.61,393.7 1787.4,380.91 C108.2@1787.4,367.13
NetC109_2: C109.2 U20.15 | length 54.1
  Top Layer w11.81: U20.15@1794.29,409.45 1794.29,396.29 1822.83,367.74 C109.2@1822.83,367.13
NetC110_2: C110.2 U20.9 | length 77.4
  Top Layer w3.94: C110.2@1635.83,363.19 1635.83,393.7 1651.57,409.45 U20.9@1676.18,409.45
NetC111_2: C111.2 U20.16 | length 124.2
  Top Layer w11.81: U20.16@1813.98,409.45 1835.63,409.45 1873.03,372.05 1873.03,364.17 C111.2@1902.56,334.65
NetC112_2: C112.2 CN9.18 F1.2 | length 178.9
  Top Layer w11.81: F1.2@3512.8,251.97 C112.2@3559.06,251.97 3587.6,251.97 3613.19,226.38 CN9.18@3681.1,226.38
NetC113_1: C113.1 R103.2 | length 31.5
  Top Layer w11.81: C113.1@1080.71,246.06 R103.2@1080.71,277.56
NetC113_2: C113.2 CN10.4 U20.11 U22.6 | length 1154.6
  Top Layer w7.87: CN10.4@1476.38,122.05 1516.73,122.05 1518.7,124.02 1518.7,310.04 1537.4,328.74 1656.5,328.74 1715.55,387.8 U20.11@1715.55,409.45
  Top Layer w11.81: U22.6@903.54,344.49 927.17,344.49 1061.02,210.63 C113.2@1080.71,210.63 1080.71,193.9 1152.56,122.05 CN10.4@1161.42,122.05 CN10.4@1476.38,122.05
NetC117_2: C117.2 C118.2 CN1.B1 U3.6 U24.1 | length 992.5
  Top Layer w19.68: U3.6@3294.29,2183.66 3239.57,2183.66 3212.6,2210.63 3212.6,2288.39 3238.19,2313.98 3325.79,2313.98 3364.17,2352.36 3486.22,2352.36 3535.43,2303.15 CN1.B1@3542.91,2303.15
  Bottom Layer w19.68: C118.2@3305.12,2284.45 3322.83,2302.17 C117.2@3322.83,2345.47 3329.72,2352.36 3493.7,2352.36 CN1.B1@3542.91,2303.15 3544.29,2303.15 3605.31,2364.17 U24.1@3650.59,2364.17
NetC123_2: C123.2 C124.2 CN1.T1 U3.7 U25.1 | length 661.2
  Top Layer w19.68: U3.7@3294.29,2233.66 3324.21,2233.66 3393.7,2303.15 CN1.T1@3439.76,2303.15
  Bottom Layer w19.68: C124.2@3305.12,2162.4 3322.83,2180.12 C123.2@3322.83,2223.43 3329.72,2223.43 3338.38,2232.09 3367.13,2260.83 3367.13,2281.5 3388.78,2303.15 CN1.T1@3439.76,2303.15 3440.94,2303.15 3497.05,2247.05 3567.91,2247.05 3622.05,2301.18 U25.1@3650.59,2301.18
NetC133_2: C133.2 C136.2 CN5.B1 U11.6 U27.1 | length 775.9
  Top Layer w19.68: U11.6@3272.05,1696.46 U11.6@3294.29,1696.46 3345.87,1696.46 3398.62,1643.7 3493.7,1643.7 CN5.B1@3542.91,1594.49
  Bottom Layer w19.68: C133.2@3305.12,1757.87 3322.83,1740.16 C136.2@3322.83,1697.83 ; C136.2@3321.85,1697.83 C136.2@3322.83,1697.83 ; CN5.B1@3542.91,1594.49 3493.7,1643.7 3408.46,1643.7 3354.33,1697.83 C136.2@3322.83,1697.83 ; CN5.B1@3544.29,1596.46 3605.31,1657.48 U27.1@3650.59,1657.48
NetC137_2: C137.2 C138.2 CN5.T1 U11.7 U28.1 | length 909.1
  Top Layer w19.68: U11.7@3294.29,1746.46 3228.74,1746.46 3202.76,1720.47 3202.76,1637.8 3246.06,1594.49 CN5.T1@3439.76,1594.49
  Bottom Layer w19.68: C138.2@3305.12,1600.39 3322.83,1618.11 C137.2@3322.83,1661.42 3338.58,1661.42 3405.51,1594.49 CN5.T1@3439.76,1594.49 ; CN5.T1@3440.94,1596.46 3498.03,1539.37 3566.93,1539.37 3622.05,1594.49 U28.1@3650.59,1594.49
NetC166_2: C166.2 C167.2 CN7.A4 CN7.A9 CN7.B4 CN7.B9 R150.1 U30.1 | length 1168
  Top Layer w11.81: CN7.A4@3599.21,1044.29 3646.46,1044.29 CN7.B9@3648.43,1046.26 ; CN7.A9@3599.21,1142.72 3646.46,1142.72 CN7.B4@3648.43,1140.75
  Signal Layer 2 w23.62: CN7.B9@3647.58,1046.26 3618.11,1046.26 3604.33,1060.04 3604.33,1129.92 3615.16,1140.75 CN7.B4@3648.43,1140.75
  Signal Layer 3 w23.62: CN7.B9@3647.58,1046.26 3626.97,1046.26 3615.16,1058.07 3615.16,1123.03 3632.87,1140.75 CN7.B4@3648.43,1140.75
  Signal Layer 4 w23.62: CN7.B9@3647.58,1046.26 3630.91,1046.26 3615.16,1062.01 3615.16,1128.94 3626.97,1140.75 CN7.B4@3648.43,1140.75
  Bottom Layer w23.62: CN7.B9@3648.43,1046.26 3626.97,1046.26 3592.52,1011.81 3592.52,894.69 3608.27,878.94 3727.36,878.94 3750,901.57 3750,976.38 U30.1@3741.14,985.24
  Bottom Layer w39.37: U30.1@3741.14,985.24 C167.2@3790.16,985.24 ; C167.2@3790.35,985.24 C167.2@3790.16,985.24 ; R150.1@3906.5,985.24 C166.2@3843.5,985.24 C167.2@3790.16,985.24
NetC183_2: C183.2 CN8.2 | length 59.2
  Bottom Layer w11.81: C183.2@486.22,671.26 522.83,671.26 CN8.2@538.78,687.2
NetC185_1: C185.1 C187.2 SB21.2 U34.1 U34.3 | length 382.9
  Bottom Layer w15.75: C187.2@3126.97,420.28 3149.61,420.28 3167.32,402.56 U34.1@3181.1,402.56 3181.1,452.76 3166.34,467.52 SB21.2@3163.39,467.52 ; SB21.2@3160.43,467.52 SB21.2@3163.39,467.52 ; U34.3@3255.91,402.56 3255.91,452.76 C185.1@3269.69,466.54 3269.69,496.06 3257.87,507.87 3174.21,507.87 3163.39,497.05 SB21.2@3163.39,467.52
NetC189_2: C189.2 U34.4 | length 62.9
  Bottom Layer w15.75: C189.2@3237.2,260.83 3237.2,281.5 3255.91,300.2 U34.4@3255.91,315.94
NetCN8_11: CN8.11 R163.2 U18.33 | length 987.4
  Top Layer w3.94: v1(996.06,940.94) 1000.98,936.02 1039.68,936.02 1040.66,935.04 U18.33@1057.09,935.04
  Bottom Layer w3.94: R163.2@188.98,729.33 188.98,778.54 CN8.11@188.78,778.74 287.01,876.97 810.04,876.97 870.08,937.01 988.19,937.01 992.13,940.94 v1(996.06,940.94)
NetCN8_12: CN8.12 R162.2 | length 59.3
  Bottom Layer w3.94: R162.2@82.68,730.31 82.68,752.56 CN8.12@108.86,778.74
NetCN8_13: CN8.13 R157.1 | length 745.8
  Top Layer w3.94: v1(166.34,834.65) 100.39,834.65 65.55,799.8 65.55,760.8 131.5,694.86 131.5,302.56 CN8.13@188.78,245.28
  Bottom Layer w3.94: R157.1@189.96,834.65 R157.1@190.94,835.63
  Bottom Layer w7.87: v1(166.34,834.65) R157.1@189.96,834.65
NetCN8_14: CN8.14 R156.2 U18.32 | length 1852.8
  Top Layer w3.94: CN8.14@108.86,245.28 88.58,265.55 88.58,703.74 57.68,734.65 57.68,831.3 v1(72.83,846.46) 74.67,846.46 76.63,848.43 195.19,848.43 439.29,1092.52 730.76,1092.52 744.54,1106.3 901.27,1106.3 949.02,1058.55 949.02,998.37 966.34,981.05 966.34,979.84 969.8,976.38 971.77,976.38 993.42,954.72 1001.77,954.72 1005.71,950.79 U18.32@1057.09,950.79
  Bottom Layer w3.94: v1@71.85,847.44 v1(72.83,846.46)
  Bottom Layer w7.87: R156.2@41.34,847.44 v1@71.85,847.44
NetCN11_2: CN11.2 U21.1 | length 362.7
  Top Layer w3.94: CN11.2@2946.85,163.39 2946.85,201.77 2955.71,210.63 2955.71,327.76 3004.92,376.97 3054.13,376.97 3058.07,380.91 3058.07,384.84 3042.32,400.59 U21.1@3042.32,444.69
NetCN11_3: CN11.3 R93.1 U21.3 | length 485
  Top Layer w3.94: CN11.3@2972.44,163.39 2972.44,201.77 2963.58,210.63 2963.58,324.49 3008.18,369.09 3058.07,369.09 3066.93,377.95 3066.93,386.81 3081.69,401.57 U21.3@3081.69,444.69 3081.69,469.49 3077.76,473.43 3031.5,473.43 3002.95,444.88 R93.1@2998.03,444.88
NetCN13_8: CN13.8 R4.1 | length 91.5
  Top Layer w11.81: R4.1@2589.92,2334.09 2631.46,2334.09 v1(2632.01,2334.65)
  Bottom Layer w11.81: CN13.8@2589.92,2351.81 2607.09,2334.65 v1(2632.01,2334.65)
NetCN15_11: CN15.11 R13.2 | length 496.3
  Top Layer w3.94: R13.2@594.49,2058.07 R13.2@596.46,2056.1
  Top Layer w7.87: R13.2@594.49,2058.07 v1(594.49,2084.65)
  Bottom Layer w3.94: CN15.11@234.25,2044.29 234.25,2074.8 242.13,2082.68 253.94,2082.68 324.8,2153.54 515.75,2153.54 529.53,2139.76 561.02,2139.76 595.47,2105.31 v1@595.47,2082.68
NetCN17_5: CN17.5 SB23.2 SB24.2 | length 395.1
  Bottom Layer w11.81: CN17.5@1129.92,451.79 1270.65,451.79 1290.35,432.09 1290.35,375 1352.36,312.99 SB24.2@1378.94,312.99 SB23.2@1434.06,312.99
NetCN17_6: CN17.6 SB25.2 SB26.2 | length 420.8
  Bottom Layer w11.81: CN17.6@1029.92,586.79 1029.92,497.44 1081.69,445.67 1081.69,364.17 1132.87,312.99 SB26.2@1182.09,312.99 SB25.2@1237.2,312.99
NetCN95_1: CN95.1 U13.P4 | length 744.7
  Top Layer w15.75: CN95.1@1711.61,2185.04 CN95.1@1717.52,2179.13
  Signal Layer 3 w3.94: v1(1692.91,1496.06) 1712.6,1515.75 1712.6,2106.5 1698.82,2120.28 1698.82,2171.26 CN95.1@1712.6,2185.04
  Bottom Layer w3.94: v1(1692.91,1496.06) U13.P4@1712.6,1515.75
NetD1_2: D1.2 D2.2 SB21.1 | length 379.6
  Bottom Layer w15.75: D2.2@3050.98,467.52 3105.31,467.52 ; SB21.1@3117.13,467.52 3105.31,467.52 ; D1.2@3329.72,478.15 3329.72,505.91 3304.13,531.5 3127.95,531.5 3105.31,508.86 3105.31,467.52
NetL4_1: L4.1 U8.34 | length 109.7
  Top Layer w9.84: U8.34@241.14,1961.61 241.14,1975.39 258.86,1993.11 L4.1@329.72,1993.11
NetL8_2: L8.2 U3.2 U11.2 | length 1091.2
  Top Layer w23.62: v2@3034.06,2233.66 v2(3034.45,2233.27) ; L8.2@3035.43,1746.06 L8.2@3035.83,1746.46
  Top Layer w39.37: v2(3004.92,2233.27) v2(3034.45,2233.27) ; v2@3005.37,1784.98 3034.98,1784.98 3035.43,1785.43 L8.2@3035.43,1746.06 ; v2@3034.06,2233.66 U3.2@3107.28,2233.66 ; L8.2@3035.83,1746.46 U11.2@3107.28,1746.46
  Signal Layer 1 w23.62: v2(3004.92,1785.43) 3035.52,1785.43 v2(3035.97,1785.88) ; v2(3004.92,2233.27) v2(3034.45,2233.27)
  Signal Layer 2 w23.62: v2(3004.92,1785.43) 3005.37,1785.88 v2(3035.97,1785.88) ; v2(3004.92,2233.27) v2(3034.45,2233.27)
  Signal Layer 3 w39.37: 3004.92,2203.74 3004.92,2076.77 3035.97,2045.72 3035.97,1815.58 ; 3004.92,2203.74 v2(3004.92,2233.27) v2(3034.45,2233.27) 3004.92,2203.74 ; 3035.97,1815.58 v2(3035.97,1785.88) 3006.27,1785.88 3035.97,1815.58
  Signal Layer 4 w23.62: v2(3004.92,1785.43) 3035.52,1785.43 v2(3035.97,1785.88) ; v2(3004.92,2233.27) v2(3034.45,2233.27)
  Bottom Layer w23.62: v2(3004.92,1785.43) 3035.52,1785.43 v2(3035.97,1785.88) ; v2(3004.92,2233.27) v2(3034.45,2233.27)
NetLD1_1: LD1.1 R21.1 | length 44.3
  Top Layer w7.87: LD1.1@2406.5,1803.15 2418.31,1814.96 R21.1@2445.87,1814.96
NetLD2_1: LD2.1 R41.1 | length 43.3
  Top Layer w23.62: LD2.1@352.36,1465.55 R41.1@395.67,1465.55
NetLD3_1: LD3.1 R67.2 U18.34 | length 743
  Top Layer w3.94: R67.2@531.5,996.06 535.43,996.06 535.43,1026.57 592.52,1083.66 912.77,1083.66 912.77,1080.31 932.09,1060.99 932.09,1004.72 954.02,982.79 954.02,981.58 967.1,968.5 968.3,968.5 982.28,954.52 982.28,935.24 990.36,927.17 1009.84,927.17 1011.81,925.2 1039.37,925.2 1045.28,919.29 U18.34@1057.09,919.29
  Top Layer w11.81: LD3.1@483.27,996.06 R67.2@531.5,996.06
NetLD3_2: LD3.2 R66.2 | length 49.2
  Top Layer w11.81: R66.2@375,996.06 LD3.2@424.21,996.06
NetLD4_2: LD4.2 R89.1 | length 57.1
  Top Layer w3.94: LD4.2@3184.06,399.61 R89.1@3184.06,456.69
NetLD4_3: LD4.3 R90.1 | length 57.1
  Top Layer w3.94: LD4.3@3243.11,399.61 R90.1@3243.11,456.69
NetLD5_1: LD5.1 R105.1 | length 39.4
  Top Layer w11.81: LD5.1@1862.2,227.36 R105.1@1862.2,266.73
NetLD6_1: LD6.1 R106.1 | length 39.4
  Top Layer w11.81: LD6.1@2179.13,227.36 R106.1@2179.13,266.73
NetLD7_1: LD7.1 R107.2 | length 39.4
  Top Layer w11.81: LD7.1@2512.8,227.36 R107.2@2512.8,266.73
NetLD8_1: LD8.1 R108.2 | length 50.2
  Top Layer w11.81: LD8.1@2677.17,216.54 R108.2@2677.17,266.73
NetLD9_1: LD9.1 R114.1 | length 44.3
  Bottom Layer w11.81: LD9.1@2764.76,2223.43 R114.1@2809.06,2223.43
NetLD9_2: LD9.2 T4.3 | length 59.1
  Bottom Layer w11.81: T4.3@2646.65,2223.43 LD9.2@2705.71,2223.43
NetLE1_1: LE1.1 U18.30 | length 225.3
  Top Layer w7.87: v1(1044.29,1011.81) 1051.18,1011.81 1070.87,992.13 U18.30@1082.68,992.13
  Bottom Layer w7.87: LE1.1@908.46,1062.99 908.46,1031.5 LE1.1@932.09,1007.87
  Bottom Layer w11.81: LE1.1@932.09,1007.87 936.02,1011.81 v1(1044.29,1011.81)
NetQ1_2: Q1.2 Q1.5 Q1.6 R45.2 | length 154.1
  Top Layer w11.81: R45.2@467.52,1365.16 467.52,1371.06 478.35,1381.89 Q1.6@478.35,1414.37 Q1.5@478.35,1439.96 Q1.2@553.15,1439.96
NetR18_1: R18.1 U7.27 | length 48.2
  Top Layer w11.81: R18.1@2481.3,1856.3 U7.27@2529.53,1856.3
NetR21_2: R21.2 R23.2 U7.28 | length 124
  Top Layer w7.87: R23.2@2481.3,1773.62 R21.2@2481.3,1814.96 2493.11,1826.77 U7.28@2559.06,1826.77
NetR24_2: R24.2 U7.35 | length 84.3
  Top Layer w3.94: U7.35@2696.85,1826.77 2696.85,1798.23 2706.69,1788.39 2718.5,1788.39 2736.22,1770.67 R24.2@2741.14,1770.67
NetR29_2: R29.2 U7.32 | length 142.9
  Top Layer w3.94: R29.2@2615.16,1694.88 2639.76,1719.49 2639.76,1824.8 U7.32@2637.8,1826.77
NetR30_2: R30.2 U7.33 | length 138
  Top Layer w3.94: R30.2@2656.5,1694.88 2649.61,1701.77 2649.61,1805.12 2657.48,1812.99 U7.33@2657.48,1826.77
NetR31_2: R31.2 R32.1 U12.3 | length 142.8
  Top Layer w11.81: R31.2@2973.43,1642.72 R32.1@3014.76,1642.72 3019.68,1637.8 U12.3@3019.68,1543.31
NetR34_1: R34.1 U12.1 | length 116.4
  Top Layer w7.87: U12.1@3059.06,1543.31 3059.06,1552.17 3074.8,1567.91 3131.89,1567.91 3147.64,1583.66 R34.1@3147.64,1589.57
NetR35_1: R35.1 U12.5 | length 58.2
  Top Layer w7.87: R35.1@2946.85,1587.6 2946.85,1586.61 2980.31,1553.15 U12.5@2980.31,1543.31
NetR36_2: R36.2 U12.6 | length 69.9
  Top Layer w11.81: R36.2@2890.75,1543.31 U12.6@2960.63,1543.31
NetR43_2: R43.2 U12.20 | length 64.5
  Top Layer w7.87: U12.20@3084.65,1438.98 3091.39,1438.98 3104.33,1426.03 3104.33,1419.29 3124.02,1399.61 R43.2@3124.02,1394.68
NetR46_2: R46.2 U12.13 | length 46.3
  Top Layer w3.94: R46.2@2955.71,1349.41 2960.63,1354.33 U12.13@2960.63,1393.7
NetR58_2: R58.2 U18.27 | length 105.2
  Top Layer w3.94: U18.27@1129.92,992.13 1129.92,1087.6 R58.2@1136.81,1094.49
NetR59_2: R59.2 U18.26 | length 146.6
  Top Layer w3.94: U18.26@1145.67,992.13 1145.67,1070.87 1169.29,1094.49 R59.2@1203.74,1094.49
NetR60_2: R60.2 U18.25 | length 189.7
  Top Layer w3.94: U18.25@1161.42,992.13 1161.42,1057.09 1182.87,1078.54 1221.26,1078.54 1237.2,1094.49 R60.2@1270.67,1094.49
NetR61_2: R61.2 U18.24 | length 237.6
  Top Layer w3.94: U18.24@1177.17,992.13 1177.17,1052.17 1195.67,1070.67 1279.33,1070.67 1302.17,1093.5 R61.2@1337.6,1093.5
NetR62_2: R62.2 U18.23 | length 286.5
  Top Layer w3.94: U18.23@1192.91,992.13 1192.91,1048.23 1207.48,1062.8 1283.27,1062.8 1297.24,1076.77 1353.35,1076.77 1370.08,1093.5 R62.2@1404.53,1093.5
NetR63_2: R63.2 U18.22 | length 333.4
  Top Layer w3.94: U18.22@1208.66,992.13 1208.66,1039.37 1224.21,1054.92 1286.53,1054.92 1300.51,1068.9 1356.61,1068.9 1363.5,1075.79 1419.29,1075.79 1437.01,1093.5 R63.2@1472.44,1093.5
NetR64_2: R64.2 R69.1 U18.36 | length 296.6
  Top Layer w3.94: 902.56,906.5 963.74,906.5 969.29,900.95 969.29,900.79 976.38,893.7 1051.18,893.7 U18.36@1057.09,887.8
  Top Layer w5.12: R64.2@849.41,1018.7 849.41,1013.78 873.03,990.16 873.03,961.61 R69.1@902.56,932.09 902.56,906.5
NetR68_2: R68.2 U18.37 | length 265.8
  Top Layer w3.94: 960.83,897.44 973.38,884.88 1026.09,884.88 1038.93,872.05 U18.37@1057.09,872.05
  Top Layer w5.12: R68.2@849.41,973.43 849.41,968.5 880.91,937.01 880.91,914.37 897.83,897.44 960.83,897.44
NetR70_1: R70.1 U14.56 | length 59.5
  Top Layer w11.81: U14.56@3010.83,924.21 3045.28,924.21 R70.1@3062.99,906.5
NetR71_1: R71.1 TP31.1 U13.N2 | length 325.3
  Bottom Layer w3.54: TP31.1@1742.13,1145.67 1732.28,1155.51 1732.28,1193.39 1737.99,1199.1 1737.99,1220.08 1756.1,1238.19 R71.1@1759.84,1238.19 1759.84,1253.94 1736.22,1277.56 1736.22,1421.26 U13.N2@1751.97,1437.01
NetR80_2: R80.2 U19.3 | length 229
  Top Layer w3.94: R80.2@2557.09,795.28 2557.09,790.35 2575.79,771.65 2575.79,759.84 2648.62,687.01 2648.62,648.62 2638.78,638.78 U19.3@2608.27,638.78
NetR81_1: R81.1 U19.2 | length 167.6
  Top Layer w3.94: R81.1@2557.09,753.94 2570.56,753.94 2640.75,683.75 2640.75,663.39 2635.83,658.46 U19.2@2608.27,658.46
NetR85_1: R85.1 U20.3 | length 98.4
  Top Layer w3.94: R85.1@1561.02,558.07 1565.94,558.07 1589.57,534.45 U20.3@1649.61,534.45
NetR86_1: R86.1 U20.2 | length 48.9
  Top Layer w3.94: R86.1@1602.36,558.07 1606.3,554.13 U20.2@1649.61,554.13
NetR87_1: R87.1 U20.4 | length 58.1
  Top Layer w11.81: R87.1@1591.54,514.76 U20.4@1649.61,514.76
NetR93_2: R93.2 T3.2 | length 266.8
  Top Layer w3.94: v1(2813.98,347.44) 2831.69,365.16 2948.82,365.16 2993.11,409.45 R93.2@2998.03,409.45
  Bottom Layer w3.94: T3.2@2813.98,290.35 v1(2813.98,347.44)
NetR99_2: R99.2 R104.1 R112.2 T3.1 | length 270.1
  Top Layer w11.81: v1(2735.24,234.25) R112.2@2776.57,234.25 R104.1@2776.57,269.69 2818.9,269.69 2861.22,312.01 R99.2@2861.22,345.47
  Bottom Layer w11.81: v1(2735.24,234.25) 2735.24,286.42 T3.1@2739.17,290.35
NetR101_1: R101.1 SW1.3 | length 1979.6
  Top Layer w3.94: R101.1@2263.78,313.98 2263.78,340.55 2269.68,346.46 2377.36,346.46 2403.54,320.28 v1(2403.54,288.39)
  Signal Layer 2 w3.94: v1(2403.54,288.39) 2403.54,311.02 2452.76,360.24 2497.05,360.24 2543.31,406.5 2618.11,406.5 2716.93,505.31 3095.08,505.31 3436.02,164.37 3680.12,164.37 3700.79,143.7 3769.68,143.7 3771.65,141.73 3791.34,161.42 3846.46,161.42 v1(3848.23,159.65)
  Bottom Layer w3.94: v1(3848.23,159.65) SW1.3@3848.23,220.47
NetR102_1: R102.1 SW1.4 | length 1703.8
  Top Layer w3.94: v1(2370.08,288.39) R102.1@2370.08,313.98
  Signal Layer 2 w3.94: v1(2370.08,288.39) 2449.41,367.72 2493.95,367.72 2540.21,413.98 2615.01,413.98 2713.83,512.8 3210.63,512.8 3512.8,210.63 3697.24,210.63 v1(3748.23,159.65)
  Bottom Layer w3.94: v1(3748.23,159.65) SW1.4@3748.23,220.47
NetR119_2: R119.2 R120.2 T4.1 | length 103.2
  Bottom Layer w11.81: R120.2@2469.49,2216.54 R119.2@2505.91,2216.54 2521.65,2216.54 2552.17,2186.02 T4.1@2560.04,2186.02
NetR120_1: R120.1 SB6.2 | length 48.2
  Bottom Layer w11.81: R120.1@2434.06,2216.54 SB6.2@2434.06,2264.76
NetR127_1: R127.1 R129.2 SB7.2 U7.22 | length 209.8
  Top Layer w3.94: v1(2481.3,2021.65) 2481.3,1981.3 2507.87,1954.72 U7.22@2529.53,1954.72
  Bottom Layer w3.94: R129.2@2458.66,2021.65 v1(2481.3,2021.65) R127.1@2512.8,2021.65 SB7.2@2568.9,2021.65
NetR134_1: R134.1 R137.2 SB8.2 U7.24 | length 186.6
  Top Layer w3.94: v1(2483.27,1915.35) U7.24@2529.53,1915.35
  Bottom Layer w3.94: R137.2@2458.66,1921.26 2464.57,1915.35 v1(2483.27,1915.35) 2509.84,1915.35 R134.1@2512.8,1918.31 2517.72,1918.31 2535.43,1936.02 2535.43,1949.8 2540.35,1954.72 2561.02,1954.72 2568.9,1962.6
NetR139_2: R139.2 R140.1 U7.25 | length 119.7
  Top Layer w3.94: v1(2483.27,1893.7) 2483.27,1892.72 2486.22,1895.67 U7.25@2529.53,1895.67
  Bottom Layer w3.94: R140.1@2455.71,1876.97 2455.71,1879.92 2469.49,1893.7 v1(2483.27,1893.7) ; v1@2482.28,1894.69 2498.03,1894.69 2501.97,1890.75 2501.97,1886.81 R139.2@2508.86,1879.92
NetR149_2: R149.2 U14.72 | length 63.9
  Top Layer w11.81: U14.72@3013.78,1239.17 v1(3045.28,1239.17)
  Bottom Layer w11.81: R149.2@3017.72,1227.36 3029.53,1239.17 v1(3045.28,1239.17)
NetR150_2: R150.2 T2.5 T2.6 T2.7 T2.8 U12.18 | length 1404
  Top Layer w11.81: U12.18@3059.06,1393.7 3059.06,1385.83 3161.42,1283.46 3161.42,1208.66 3204.72,1165.35 3355.31,1165.35 3417.32,1227.36
  Top Layer w39.37: 3443.9,1267.72 v2(3554.13,1267.72) v2(3579.72,1267.72)
  Signal Layer 1 w23.62: v2(3554.13,1267.72) v2(3579.72,1267.72)
  Signal Layer 2 w23.62: v2(3554.13,1267.72) v2(3579.72,1267.72)
  Signal Layer 3 w23.62: v2(3554.13,1267.72) v2(3579.72,1267.72)
  Signal Layer 4 w23.62: v2(3554.13,1267.72) v2(3579.72,1267.72)
  Bottom Layer w39.37: R150.2@3906.5,1040.35 3906.5,1113.19 3805.12,1214.57 3805.12,1239.17 3731.3,1312.99 3625,1312.99 ; 3625,1312.99 v2(3579.72,1267.72) v2(3554.13,1267.72) 3554.13,1281.5 3585.63,1312.99 3625,1312.99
